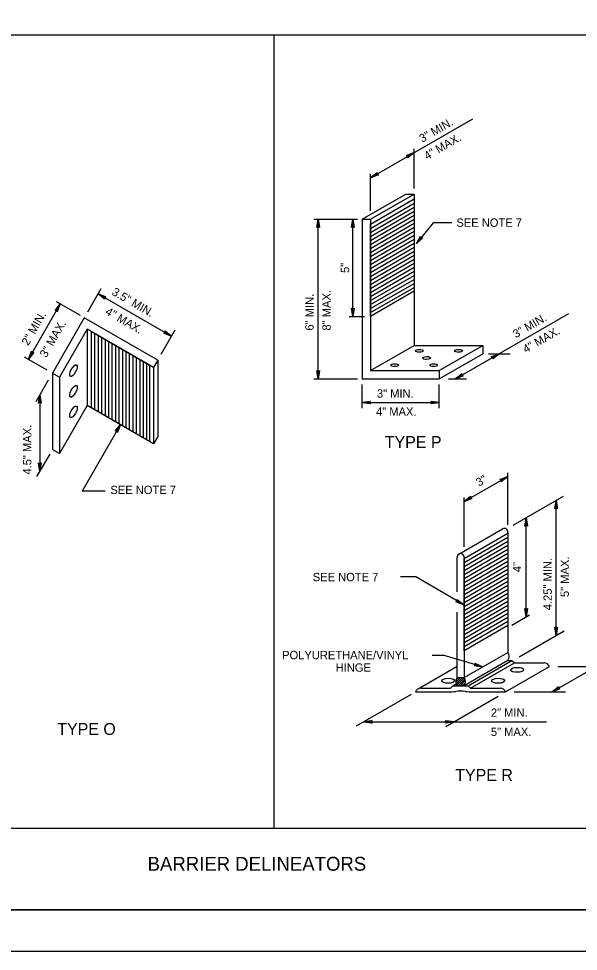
# Model space of a CAD drawing. Extents: x 640253 to 641999, y 298458 to 299646.
# Drawn here: x 640460.4 to 640662, y 298457.6 to 298793.5 of the extents above; entities that cross this region are included whole.
import ezdxf

# ---------------------------------------------------------------- set-up
doc = ezdxf.new("R2010")
doc.units = 0
for name, color, linetype in [('1', 7, 'Continuous'), ('2', 7, 'Continuous'), ('PLT-BNDY', 7, 'Continuous')]:
    doc.layers.add(name, color=color, linetype=linetype)

msp = doc.modelspace()

# ---------------------------------------------------------------- linework, layer by layer
at = {"layer": '1'}
for p, q in [((640293.31, 298787.67), (641079.31, 298787.67)), ((640552.4, 298501.97), (640552.4, 298787.67)), ((640318.26, 298501.97), (640782.88, 298501.97)), ((641079.31, 298472.63), (640293.31, 298472.63)), ((640293.31, 298472.63), (640879.31, 298472.63))]:
    msp.add_line(p, q, dxfattribs=at)
at = {"layer": '2'}
for p, q in [((640587.19, 298736.22), (640624, 298757.47)), ((640602.93, 298732.38), (640602.93, 298746.61)), ((640587.19, 298724.38), (640587.19, 298737.68)), ((640584.12, 298721.28), (640599.86, 298730.37)), ((640587.12, 298721.28), (640602.86, 298730.37)), ((640599.86, 298730.37), (640602.86, 298730.37)), ((640602.86, 298730.37), (640602.86, 298675.87)), ((640587.12, 298717.99), (640602.86, 298727.08)), ((640587.12, 298716.54), (640602.86, 298725.63)), ((640587.12, 298715.1), (640602.86, 298724.19)), ((640566.74, 298721.28), (640582.49, 298721.28)), ((640568.28, 298663.78), (640568.28, 298721.28)), ((640580.82, 298686.28), (640580.82, 298721.28)), ((640584.12, 298721.28), (640587.12, 298721.28)), ((640584.12, 298721.28), (640584.12, 298663.78)), ((640587.12, 298713.66), (640602.86, 298722.75)), ((640587.12, 298712.21), (640602.86, 298721.3)), ((640587.12, 298721.28), (640587.12, 298666.78)), ((640587.12, 298710.77), (640602.86, 298719.86)), ((640609.71, 298719.96), (640603.7, 298712.54)), ((640616.48, 298719.96), (640609.71, 298719.96)), ((640587.12, 298719.28), (640587.35, 298719.68)), ((640587.12, 298719.32), (640587.32, 298719.66)), ((640587.12, 298709.33), (640602.86, 298718.41)), ((640587.12, 298707.88), (640602.86, 298716.97)), ((640587.12, 298706.44), (640602.86, 298715.53)), ((640587.12, 298705), (640602.86, 298714.09)), ((640587.12, 298703.55), (640602.86, 298712.64)), ((640587.12, 298702.11), (640602.86, 298711.2)), ((640587.12, 298700.67), (640602.86, 298709.75)), ((640587.12, 298699.22), (640602.86, 298708.31)), ((640587.12, 298697.78), (640602.86, 298706.87)), ((640587.12, 298696.34), (640602.86, 298705.43)), ((640587.12, 298694.89), (640602.86, 298703.98)), ((640587.12, 298693.45), (640602.86, 298702.54)), ((640587.12, 298692.01), (640602.86, 298701.09)), ((640587.12, 298690.56), (640602.86, 298699.65)), ((640587.12, 298689.12), (640602.86, 298698.21)), ((640587.12, 298687.68), (640602.86, 298696.76)), ((640489.99, 298696.18), (640485.17, 298687.84)), ((640488.99, 298694.45), (640515.45, 298679.17)), ((640475.38, 298690.81), (640463.88, 298670.9)), ((640473.86, 298691.69), (640482.49, 298686.7)), ((640579.47, 298686.28), (640585.04, 298686.28)), ((640617.72, 298663.78), (640658.57, 298687.36)), ((640484.01, 298685.83), (640472.51, 298665.91)), ((640510.48, 298670.55), (640484.01, 298685.83)), ((640485.11, 298681.73), (640475.11, 298664.41)), ((640508.98, 298667.95), (640485.11, 298681.73)), ((640485.11, 298681.73), (640485.11, 298654.23)), ((640487.74, 298680.21), (640487.74, 298652.71)), ((640488.99, 298679.49), (640488.99, 298651.99)), ((640516.7, 298681.32), (640511.64, 298672.56)), ((640490.24, 298678.77), (640490.24, 298651.27)), ((640491.49, 298678.05), (640491.49, 298650.55)), ((640492.74, 298677.32), (640492.74, 298649.83)), ((640493.99, 298676.6), (640493.99, 298649.1)), ((640495.24, 298675.88), (640495.24, 298648.38)), ((640496.49, 298675.16), (640496.49, 298647.66)), ((640497.74, 298674.44), (640497.74, 298646.94)), ((640498.99, 298673.72), (640498.99, 298646.22)), ((640500.24, 298672.99), (640500.24, 298645.5)), ((640587.12, 298666.78), (640602.86, 298675.87)), ((640602.86, 298675.87), (640627.58, 298675.87)), ((640611.84, 298666.78), (640627.58, 298675.87)), ((640611.84, 298663.78), (640627.58, 298672.87)), ((640627.58, 298675.87), (640627.58, 298672.87)), ((640629.69, 298672.87), (640637.47, 298672.87)), ((640462.36, 298671.77), (640470.52, 298667.06)), ((640501.49, 298672.27), (640501.49, 298644.77)), ((640502.74, 298671.55), (640502.74, 298644.05)), ((640503.99, 298670.83), (640503.99, 298643.33)), ((640505.24, 298670.11), (640505.24, 298642.61)), ((640506.49, 298669.38), (640506.49, 298641.89)), ((640510.48, 298670.55), (640508.98, 298667.95)), ((640510.48, 298670.55), (640510.48, 298643.05)), ((640508.98, 298667.95), (640508.98, 298640.45)), ((640587.12, 298666.78), (640611.84, 298666.78)), ((640611.84, 298666.78), (640611.84, 298663.78)), ((640471.02, 298663.32), (640466.52, 298655.53)), ((640472.51, 298665.91), (640475.11, 298664.41)), ((640472.51, 298665.91), (640472.51, 298638.41)), ((640475.11, 298664.41), (640475.11, 298636.91)), ((640566.74, 298663.78), (640582.49, 298663.78)), ((640584.12, 298663.78), (640611.84, 298663.78)), ((640615.31, 298663.78), (640621.72, 298663.78)), ((640584.12, 298653.23), (640584.12, 298661.74)), ((640611.84, 298653.23), (640611.84, 298661.74)), ((640467.96, 298658.03), (640467.96, 298630.53)), ((640485.11, 298654.23), (640475.11, 298636.91)), ((640508.98, 298640.45), (640485.11, 298654.23)), ((640584.12, 298655.27), (640611.84, 298655.27)), ((640497.06, 298647.33), (640483.19, 298623.3)), ((640510.48, 298643.05), (640508.98, 298640.45)), ((640471.54, 298636.74), (640466.84, 298628.59)), ((640472.51, 298638.41), (640475.11, 298636.91)), ((640636.6, 298611.27), (640636.6, 298629.99)), ((640620.86, 298619.6), (640636.6, 298628.69)), ((640491.5, 298623.3), (640483.19, 298623.3)), ((640620.86, 298603.34), (640620.86, 298621.06)), ((640638.58, 298611.11), (640656.73, 298621.59)), ((640654.02, 298571.37), (640654.02, 298620.03)), ((640643.19, 298578.08), (640643.19, 298613.77)), ((640618.97, 298600.71), (640634.72, 298609.8)), ((640620.86, 298597.71), (640636.6, 298606.8)), ((640636.6, 298608.5), (640636.6, 298565.29)), ((640620.86, 298596.27), (640636.6, 298605.36)), ((640620.86, 298594.82), (640636.6, 298603.91)), ((640620.86, 298593.38), (640636.6, 298602.47)), ((640618.36, 298587.14), (640618.36, 298599.41)), ((640620.86, 298591.94), (640636.6, 298601.02)), ((640620.86, 298590.49), (640636.6, 298599.58)), ((640620.86, 298599.41), (640620.86, 298556.2)), ((640620.86, 298598.88), (640621.08, 298599.28)), ((640620.86, 298598.91), (640621.05, 298599.26)), ((640620.86, 298589.05), (640636.6, 298598.14)), ((640620.86, 298587.61), (640636.6, 298596.69)), ((640603.45, 298592.49), (640597.95, 298592.49)), ((640620.73, 298582.38), (640603.45, 298592.49)), ((640620.86, 298586.16), (640636.6, 298595.25)), ((640620.86, 298584.72), (640636.6, 298593.81)), ((640620.86, 298583.28), (640636.6, 298592.36)), ((640620.86, 298581.83), (640636.6, 298590.92)), ((640620.86, 298580.39), (640636.6, 298589.48)), ((640620.86, 298578.94), (640636.6, 298588.03)), ((640620.86, 298577.5), (640636.6, 298586.59)), ((640620.86, 298576.06), (640636.6, 298585.15)), ((640620.86, 298574.62), (640636.6, 298583.7)), ((640620.86, 298573.17), (640636.6, 298582.26)), ((640618.36, 298556.2), (640618.36, 298579.81)), ((640620.86, 298571.73), (640636.6, 298580.82)), ((640620.86, 298570.28), (640636.6, 298579.37)), ((640638.07, 298575.12), (640644.5, 298578.83)), ((640620.86, 298568.84), (640636.6, 298577.93)), ((640620.86, 298567.4), (640636.6, 298576.49)), ((640640.76, 298563.72), (640656.91, 298573.04)), ((640620.86, 298556.2), (640636.6, 298565.29)), ((640613.67, 298564.19), (640609.34, 298564.19)), ((640627.46, 298560.15), (640613.67, 298564.19)), ((640636.6, 298562.41), (640620.86, 298553.31)), ((640622.36, 298553.31), (640638.1, 298562.41)), ((640636.6, 298562.41), (640638.1, 298562.41)), ((640638.1, 298562.41), (640638.98, 298561.53)), ((640652.59, 298551.06), (640674.47, 298563.69)), ((640604.27, 298552.17), (640618.36, 298560.31)), ((640623.23, 298552.44), (640638.98, 298561.53)), ((640635.85, 298551.06), (640651.6, 298560.16)), ((640638.98, 298561.53), (640649.7, 298561.53)), ((640654.65, 298560.16), (640671.23, 298560.16)), ((640617.88, 298554.53), (640619.55, 298556.2)), ((640617.95, 298555.31), (640618.84, 298556.2)), ((640618.01, 298553.96), (640620.26, 298556.2)), ((640618.24, 298553.48), (640620.9, 298556.14)), ((640618.36, 298556.2), (640620.86, 298556.2)), ((640618.78, 298553.31), (640621.17, 298555.7)), ((640605.26, 298552.44), (640615.98, 298552.44)), ((640616.86, 298553.31), (640615.98, 298552.44)), ((640616.86, 298553.31), (640617.98, 298553.96)), ((640616.86, 298553.31), (640622.36, 298553.31)), ((640619.49, 298553.31), (640621.32, 298555.15)), ((640620.2, 298553.31), (640621.33, 298554.45)), ((640620.86, 298553.31), (640620.86, 298553.32)), ((640622.36, 298553.31), (640623.23, 298552.44)), ((640623.23, 298552.44), (640633.95, 298552.44)), ((640582.11, 298538.79), (640601.98, 298550.27)), ((640603.36, 298551.06), (640615.26, 298551.06)), ((640614.25, 298538.6), (640633.17, 298549.52)), ((640623.96, 298551.06), (640635.85, 298551.06)), ((640638.93, 298551.06), (640657.37, 298551.06)), ((640584.7, 298540.29), (640650.57, 298540.29))]:
    msp.add_line(p, q, dxfattribs=at)
for points in [[(640600.28, 298744.19), (640600.48, 298744.07), (640602.93, 298745.31), (640600.28, 298744.19), (640600.09, 298744.23), (640602.93, 298745.31), (640600.62, 298743.82), (640600.64, 298743.59), (640602.93, 298745.31), (640600.57, 298743.39), (640600.64, 298743.59)], [(640589.84, 298737.33), (640589.64, 298737.46), (640587.19, 298736.22), (640589.84, 298737.33), (640590.03, 298737.3), (640587.19, 298736.22), (640589.5, 298737.71), (640589.48, 298737.93), (640587.19, 298736.22), (640589.55, 298738.13), (640589.48, 298737.93)], [(640567.92, 298718.43), (640568.13, 298718.53), (640568.28, 298721.28), (640567.92, 298718.43), (640567.8, 298718.28), (640568.28, 298721.28), (640568.42, 298718.53), (640568.62, 298718.43), (640568.28, 298721.28), (640568.76, 298718.28), (640568.62, 298718.43)], [(640580.46, 298718.43), (640580.67, 298718.53), (640580.82, 298721.28), (640580.46, 298718.43), (640580.34, 298718.28), (640580.82, 298721.28), (640580.96, 298718.53), (640581.16, 298718.43), (640580.82, 298721.28), (640581.3, 298718.28), (640581.16, 298718.43)], [(640605.78, 298714.53), (640605.55, 298714.58), (640603.7, 298712.54), (640605.78, 298714.53), (640605.97, 298714.56), (640603.7, 298712.54), (640605.33, 298714.75), (640605.23, 298714.96), (640603.7, 298712.54), (640605.22, 298715.17), (640605.23, 298714.96)], [(640491.28, 298692.71), (640491.29, 298692.94), (640488.99, 298694.45), (640491.28, 298692.71), (640491.35, 298692.53), (640488.99, 298694.45), (640491.44, 298693.19), (640491.62, 298693.32), (640488.99, 298694.45), (640491.83, 298693.36), (640491.62, 298693.32)], [(640473.64, 298688.52), (640473.87, 298688.51), (640475.38, 298690.81), (640473.64, 298688.52), (640473.46, 298688.46), (640475.38, 298690.81), (640474.12, 298688.37), (640474.25, 298688.18), (640475.38, 298690.81), (640474.29, 298687.98), (640474.25, 298688.18)], [(640581.18, 298689.13), (640580.97, 298689.03), (640580.82, 298686.28), (640581.18, 298689.13), (640581.3, 298689.28), (640580.82, 298686.28), (640580.69, 298689.03), (640580.48, 298689.13), (640580.82, 298686.28), (640580.34, 298689.28), (640580.48, 298689.13)], [(640513.16, 298680.91), (640513.15, 298680.68), (640515.45, 298679.17), (640513.16, 298680.91), (640513.1, 298681.09), (640515.45, 298679.17), (640513.01, 298680.43), (640512.82, 298680.3), (640515.45, 298679.17), (640512.62, 298680.26), (640512.82, 298680.3)], [(640465.62, 298673.19), (640465.38, 298673.2), (640463.88, 298670.9), (640465.62, 298673.19), (640465.8, 298673.25), (640463.88, 298670.9), (640465.13, 298673.34), (640465.01, 298673.53), (640463.88, 298670.9), (640464.97, 298673.73), (640465.01, 298673.53)], [(640630.82, 298671.76), (640631.02, 298671.63), (640633.47, 298672.87), (640630.82, 298671.76), (640630.63, 298671.79), (640633.47, 298672.87), (640631.16, 298671.38), (640631.18, 298671.16), (640633.47, 298672.87), (640631.11, 298670.96), (640631.18, 298671.16)], [(640568.64, 298666.63), (640568.43, 298666.53), (640568.28, 298663.78), (640568.64, 298666.63), (640568.76, 298666.78), (640568.28, 298663.78), (640568.14, 298666.53), (640567.94, 298666.63), (640568.28, 298663.78), (640567.8, 298666.78), (640567.94, 298666.63)], [(640620.37, 298664.9), (640620.18, 298665.02), (640617.72, 298663.78), (640620.37, 298664.9), (640620.56, 298664.86), (640617.72, 298663.78), (640620.03, 298665.27), (640620.02, 298665.5), (640617.72, 298663.78), (640620.08, 298665.69), (640620.02, 298665.5)], [(640467.6, 298655.18), (640467.81, 298655.29), (640467.96, 298658.03), (640467.6, 298655.18), (640467.48, 298655.03), (640467.96, 298658.03), (640468.1, 298655.29), (640468.3, 298655.19), (640467.96, 298658.03), (640468.44, 298655.03), (640468.3, 298655.19)], [(640586.97, 298654.91), (640586.87, 298655.12), (640584.12, 298655.27), (640586.97, 298654.91), (640587.12, 298654.79), (640584.12, 298655.27), (640586.87, 298655.41), (640586.97, 298655.61), (640584.12, 298655.27), (640587.12, 298655.75), (640586.97, 298655.61)], [(640608.98, 298655.63), (640609.09, 298655.42), (640611.84, 298655.27), (640608.98, 298655.63), (640608.84, 298655.75), (640611.84, 298655.27), (640609.09, 298655.14), (640608.99, 298654.93), (640611.84, 298655.27), (640608.84, 298654.79), (640608.99, 298654.93)], [(640495.33, 298645.04), (640495.56, 298645.03), (640497.06, 298647.33), (640495.33, 298645.04), (640495.15, 298644.97), (640497.06, 298647.33), (640495.81, 298644.88), (640495.94, 298644.7), (640497.06, 298647.33), (640495.98, 298644.49), (640495.94, 298644.7)], [(640468.32, 298633.39), (640468.11, 298633.28), (640467.96, 298630.53), (640468.32, 298633.39), (640468.45, 298633.53), (640467.96, 298630.53), (640467.83, 298633.28), (640467.62, 298633.38), (640467.96, 298630.53), (640467.49, 298633.53), (640467.62, 298633.38)], [(640633.95, 298627.57), (640634.14, 298627.45), (640636.6, 298628.69), (640633.95, 298627.57), (640633.76, 298627.61), (640636.6, 298628.69), (640634.29, 298627.2), (640634.3, 298626.97), (640636.6, 298628.69), (640634.24, 298626.78), (640634.3, 298626.97)], [(640623.51, 298620.71), (640623.31, 298620.84), (640620.86, 298619.6), (640623.51, 298620.71), (640623.7, 298620.68), (640620.86, 298619.6), (640623.17, 298621.09), (640623.15, 298621.31), (640620.86, 298619.6), (640623.22, 298621.51), (640623.15, 298621.31)], [(640653.66, 298617.17), (640653.87, 298617.28), (640654.02, 298620.03), (640653.66, 298617.17), (640653.54, 298617.03), (640654.02, 298620.03), (640654.16, 298617.28), (640654.36, 298617.18), (640654.02, 298620.03), (640654.5, 298617.03), (640654.36, 298617.18)], [(640642.83, 298610.92), (640643.04, 298611.03), (640643.19, 298613.77), (640642.83, 298610.92), (640642.71, 298610.77), (640643.19, 298613.77), (640643.33, 298611.03), (640643.53, 298610.93), (640643.19, 298613.77), (640643.67, 298610.77), (640643.53, 298610.93)], [(640618.46, 298584.15), (640618.44, 298583.92), (640620.73, 298582.38), (640618.46, 298584.15), (640618.4, 298584.34), (640620.73, 298582.38), (640618.3, 298583.67), (640618.11, 298583.55), (640620.73, 298582.38), (640617.9, 298583.51), (640618.11, 298583.55)], [(640643.55, 298580.93), (640643.35, 298580.83), (640643.19, 298578.08), (640643.55, 298580.93), (640643.68, 298581.08), (640643.19, 298578.08), (640643.06, 298580.83), (640642.85, 298580.93), (640643.19, 298578.08), (640642.72, 298581.08), (640642.85, 298580.93)], [(640654.38, 298574.23), (640654.17, 298574.12), (640654.02, 298571.37), (640654.38, 298574.23), (640654.5, 298574.37), (640654.02, 298571.37), (640653.89, 298574.12), (640653.68, 298574.22), (640654.02, 298571.37), (640653.54, 298574.37), (640653.68, 298574.22)], [(640624.82, 298561.29), (640624.87, 298561.07), (640627.46, 298560.15), (640624.82, 298561.29), (640624.72, 298561.45), (640627.46, 298560.15), (640624.79, 298560.79), (640624.63, 298560.62), (640627.46, 298560.15), (640624.45, 298560.53), (640624.63, 298560.62)], [(640655.24, 298552.18), (640655.05, 298552.31), (640652.59, 298551.06), (640655.24, 298552.18), (640655.43, 298552.14), (640652.59, 298551.06), (640654.9, 298552.55), (640654.89, 298552.78), (640652.59, 298551.06), (640654.95, 298552.98), (640654.89, 298552.78)], [(640587.56, 298539.93), (640587.45, 298540.14), (640584.7, 298540.29), (640587.56, 298539.93), (640587.7, 298539.81), (640584.7, 298540.29), (640587.45, 298540.43), (640587.55, 298540.63), (640584.7, 298540.29), (640587.7, 298540.77), (640587.55, 298540.63)], [(640614.34, 298540.65), (640614.44, 298540.45), (640617.19, 298540.29), (640614.34, 298540.65), (640614.19, 298540.78), (640617.19, 298540.29), (640614.45, 298540.16), (640614.35, 298539.95), (640617.19, 298540.29), (640614.19, 298539.82), (640614.35, 298539.95)]]:
    msp.add_lwpolyline(points, dxfattribs=at)
for points in [[(640587.12, 298686.28), (640587.12, 298719.55), (640602.86, 298728.64), (640602.86, 298695.37)], [(640486.61, 298680.87), (640507.52, 298668.79), (640507.52, 298641.29), (640486.61, 298653.37)], [(640620.86, 298565.88), (640620.86, 298599.14), (640636.6, 298608.23), (640636.6, 298574.97)]]:
    msp.add_lwpolyline(points, close=True, dxfattribs=at)
for centre, radius, start, end in [((640635.35, 298608.7), 1.26, 350.9133, 119.9792), ((640619.61, 298599.61), 1.26, 350.9133, 189.0867), ((640634.82, 298563.85), 2.29, 320.9923, 39.0623), ((640649.7, 298559.53), 2, 18.187, 90), ((640620.14, 298554.76), 2.29, 140.9377, 219.0623), ((640619.08, 298554.76), 2.29, 320.9923, 39.0623), ((640605.26, 298550.44), 2, 90, 161.79), ((640633.95, 298550.44), 2, 18.21, 90), ((640615.26, 298569.81), 18.75, 270, 278.0038), ((640619.61, 298538.87), 12.5, 81.9962, 98.0038), ((640623.96, 298569.81), 18.75, 261.9962, 270)]:
    msp.add_arc(centre, radius, start, end, dxfattribs=at)
for centre, major_axis in [((640604.79, 298673.91), (1.39, 0.03)), ((640618.87, 298673.91), (1.39, 0.03)), ((640607.35, 298671.32), (1.39, 0.03)), ((640480.11, 298666.73), (-1.14, -2.07)), ((640595.82, 298668.73), (1.39, 0.03)), ((640609.91, 298668.73), (1.39, 0.03)), ((640480.11, 298659.32), (-1.14, -2.07)), ((640480.11, 298651.91), (-1.14, -2.07)), ((640639.98, 298559.01), (2.36, 0.05)), ((640615.17, 298555.06), (2.36, 0.05)), ((640633.14, 298555.06), (2.36, 0.05))]:
    msp.add_ellipse(centre, major_axis=major_axis, ratio=0.379302, dxfattribs=at)
at = {"layer": 'PLT-BNDY'}
msp.add_lwpolyline([(640253.31, 299051.63), (641094.31, 299051.63), (641094.31, 298457.63), (640253.31, 298457.63)], close=True, dxfattribs=at)

# ---------------------------------------------------------------- texts
at = {"layer": '2'}
for s, rotation, p in [('3" MIN.', 30, (640605.81, 298748.79)), ('4" MAX.', 30, (640607.5, 298742.55)), ('5"', 90, (640579.45, 298701.95)), ('3.5" MIN.', 329.9989, (640493.66, 298694.28)), ('6" MIN.', 90, (640566.64, 298681.2)), ('8" MAX.', 90, (640572.8, 298681.2)), ('2" MIN.', 59.9989, (640463.82, 298675.53)), ('4" MAX.', 329.9989, (640491.31, 298687.2)), ('3" MIN.', 30, (640639.52, 298678.37)), ('3" MAX.', 59.9989, (640470.32, 298671.21)), ('4" MAX.', 30, (640643.12, 298672.95)), ('4.5" MAX.', 89.9989, (640464.94, 298629.34)), ('3"', 30, (640626.22, 298624.93)), ('4.25" MIN.', 90, (640652.48, 298580.5)), ('5" MAX.', 90, (640658.64, 298585.22)), ('4"', 90, (640641.44, 298594.19))]:
    msp.add_text(s, height=3, rotation=rotation, dxfattribs=at).set_placement(p)
for s, height, p in [('SEE NOTE 7', 3, (640618.1, 298718.57)), ('3" MIN.', 3, (640589.47, 298657.04)), ('4" MAX.', 3, (640589.16, 298650.5)), ('TYPE P', 4.3, (640592.3, 298638.89)), ('SEE NOTE 7', 3, (640493.42, 298622.31)), ('SEE NOTE 7', 3, (640566.35, 298590.94)), ('POLYURETHANE/VINYL', 3, (640555.3, 298562.84)), ('HINGE', 3, (640574.58, 298558.34)), ('2" MIN.', 3, (640630.53, 298542.1)), ('TYPE O', 4.3, (640474.27, 298535.56)), ('5" MAX.', 3, (640630.53, 298535.19)), ('TYPE R', 4.3, (640617.68, 298518.99)), ('BARRIER DELINEATORS', 5, (640506.83, 298486.66))]:
    msp.add_text(s, height=height, dxfattribs=at).set_placement(p)

doc.saveas('drawing.dxf')
